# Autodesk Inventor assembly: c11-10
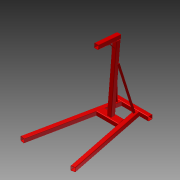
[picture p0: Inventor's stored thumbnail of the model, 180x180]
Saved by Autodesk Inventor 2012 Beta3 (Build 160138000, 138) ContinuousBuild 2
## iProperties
Created: 2011-01
Part Number: c11-10
Document SubType Name: Assembly
Designer: Beta-8540w
_SolveAssemblyDoc: Frame Generator Solve Assembly
_Version: 15.0.0
Author: Beta-8540w
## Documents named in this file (3)
- C:\Inventor 2012 Essentials\Assemblies\Chapter 11\c11-10.iam
- C:\Inventor 2012 Essentials\Assemblies\Chapter 11\Frame\Frame c11-10.iam
- C:\Inventor 2012 Essentials\Parts\Chapter 11\c11-02.ipt
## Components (2 placed, 2 different names)
1. c11-02:1
2. Frame c11-10:1 [sub-assembly]
